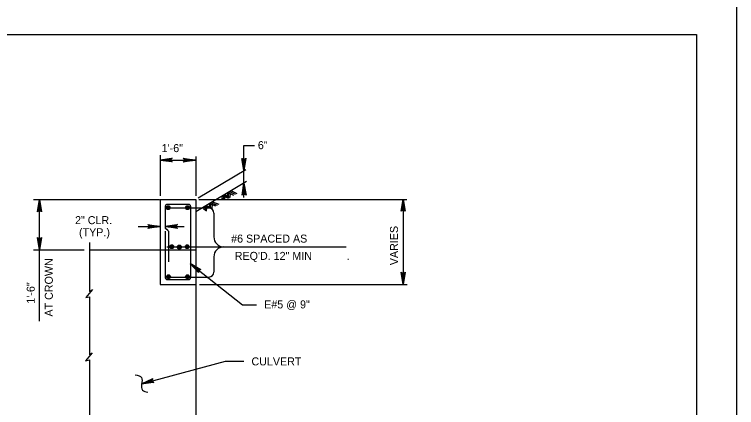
# Model space of a CAD drawing. Extents: x 639011 to 639866, y 298840 to 300028.
# Drawn here: x 639582.6 to 639852.3, y 299279.7 to 299426.3 of the extents above; entities that cross this region are included whole.
import ezdxf

# ---------------------------------------------------------------- set-up
doc = ezdxf.new("R2010")
doc.units = 0
doc.layers.add('2', color=7, linetype='Continuous')
doc.layers.add('PLT-BNDY', color=7, linetype='Continuous')

msp = doc.modelspace()

# ---------------------------------------------------------------- linework, layer by layer
at = {"layer": '2'}
for p, q in [((639051.26, 299418.83), (639837.26, 299418.83)), ((639837.26, 299418.83), (639837.26, 298854.83)), ((639668.28, 299377.41), (639672.26, 299377.41)), ((639668.28, 299368.11), (639668.28, 299377.41)), ((639636.93, 299373.81), (639636.93, 299358.66)), ((639636.93, 299373.81), (639636.93, 299358.66)), ((639650.28, 299373.36), (639650.28, 299358.66)), ((639650.28, 299373.36), (639650.28, 299358.66)), ((639636.93, 299372.01), (639641.48, 299372.77)), ((639641.25, 299372.56), (639636.93, 299372.01)), ((639636.93, 299372.01), (639641.09, 299372.24)), ((639636.93, 299372.01), (639641.1, 299372.03)), ((639636.93, 299372.01), (639650.13, 299372.01)), ((639641.1, 299371.81), (639636.93, 299372.01)), ((639636.93, 299372.01), (639641.26, 299371.49)), ((639641.49, 299371.3), (639636.93, 299372.01)), ((639641.09, 299372.24), (639641.25, 299372.56)), ((639641.1, 299371.81), (639641.09, 299372.24)), ((639641.26, 299371.49), (639641.1, 299371.81)), ((639641.48, 299372.77), (639641.25, 299372.56)), ((639641.26, 299371.49), (639641.49, 299371.3)), ((639645.8, 299372.52), (639645.57, 299372.72)), ((639645.57, 299372.72), (639650.13, 299372.01)), ((639650.13, 299372.01), (639645.58, 299371.25)), ((639645.58, 299371.25), (639645.81, 299371.46)), ((639645.8, 299372.52), (639645.96, 299372.21)), ((639650.13, 299372.01), (639645.8, 299372.52)), ((639645.81, 299371.46), (639650.13, 299372.01)), ((639645.96, 299371.77), (639645.81, 299371.46)), ((639645.96, 299372.21), (639650.13, 299372.01)), ((639645.96, 299372.21), (639645.96, 299371.77)), ((639650.13, 299372.01), (639645.96, 299371.77)), ((639650.13, 299372.01), (639645.96, 299371.99)), ((639668.28, 299368.11), (639667.52, 299372.66)), ((639667.52, 299372.66), (639667.73, 299372.43)), ((639668.04, 299372.27), (639667.73, 299372.43)), ((639667.73, 299372.43), (639668.28, 299368.11)), ((639668.48, 299372.28), (639668.04, 299372.27)), ((639668.28, 299368.11), (639668.04, 299372.27)), ((639668.28, 299368.11), (639668.26, 299372.27)), ((639668.99, 299372.67), (639668.28, 299368.11)), ((639668.28, 299368.11), (639668.8, 299372.44)), ((639668.48, 299372.28), (639668.28, 299368.11)), ((639668.8, 299372.44), (639668.48, 299372.28)), ((639668.8, 299372.44), (639668.99, 299372.67)), ((639651.18, 299357.91), (639669.01, 299368.55)), ((639668.28, 299363.46), (639668.28, 299368.11)), ((639650.28, 299352.87), (639669.17, 299364.14)), ((639667.57, 299358.9), (639668.28, 299363.46)), ((639668.28, 299363.46), (639667.76, 299359.13)), ((639668.08, 299359.29), (639668.28, 299363.46)), ((639668.28, 299358.06), (639668.28, 299363.46)), ((639668.28, 299363.46), (639668.51, 299359.29)), ((639668.83, 299359.14), (639668.28, 299363.46)), ((639668.28, 299363.46), (639669.04, 299358.9)), ((639668.28, 299363.46), (639668.3, 299359.29)), ((639662.14, 299359.95), (639661.98, 299358.69)), ((639662.13, 299359.86), (639661.98, 299358.66)), ((639662.13, 299360.01), (639664.38, 299358.96)), ((639662.19, 299359.98), (639664.38, 299358.96)), ((639662.59, 299359.79), (639662.43, 299358.51)), ((639662.73, 299360.31), (639664.98, 299359.26)), ((639662.74, 299360.3), (639664.98, 299359.26)), ((639663.28, 299360.63), (639665.58, 299359.56)), ((639663.33, 299360.61), (639665.58, 299359.56)), ((639589.68, 299357.31), (639636.78, 299357.31)), ((639589.68, 299357.31), (639636.78, 299357.31)), ((639591.22, 299352.75), (639591.93, 299357.31)), ((639591.93, 299357.31), (639591.41, 299352.98)), ((639591.73, 299353.14), (639591.93, 299357.31)), ((639591.93, 299338.56), (639591.93, 299357.31)), ((639591.93, 299357.31), (639592.16, 299353.14)), ((639592.47, 299352.99), (639591.93, 299357.31)), ((639591.93, 299357.31), (639592.69, 299352.75)), ((639591.93, 299357.31), (639591.94, 299353.14)), ((639636.93, 299357.31), (639650.28, 299357.31)), ((639636.93, 299357.31), (639636.93, 299329.56)), ((639636.93, 299357.31), (639650.28, 299357.31)), ((639636.93, 299357.31), (639636.93, 299329.56)), ((639650.28, 299357.31), (639650.28, 299228.46)), ((639651.48, 299357.31), (639729.08, 299357.31)), ((639651.48, 299357.31), (639729.08, 299357.31)), ((639660.18, 299358.81), (639660.03, 299357.46)), ((639660.18, 299358.77), (639660.03, 299357.46)), ((639660.18, 299358.81), (639662.43, 299357.76)), ((639660.21, 299358.79), (639662.43, 299357.76)), ((639660.48, 299358.96), (639662.73, 299357.91)), ((639660.48, 299358.96), (639662.73, 299357.91)), ((639660.64, 299358.59), (639660.48, 299357.31)), ((639660.63, 299358.51), (639660.48, 299357.31)), ((639660.81, 299359.15), (639663.18, 299358.21)), ((639660.93, 299359.11), (639663.18, 299358.21)), ((639661.08, 299358.39), (639660.93, 299357.01)), ((639661.08, 299358.36), (639660.93, 299357.01)), ((639662.58, 299359.71), (639662.43, 299358.51)), ((639663.18, 299359.56), (639663.03, 299358.21)), ((639663.17, 299359.52), (639663.04, 299358.27)), ((639667.76, 299359.13), (639667.57, 299358.9)), ((639667.76, 299359.13), (639668.08, 299359.29)), ((639668.08, 299359.29), (639668.51, 299359.29)), ((639668.51, 299359.29), (639668.83, 299359.14)), ((639669.04, 299358.9), (639668.83, 299359.14)), ((639727.02, 299352.9), (639727.73, 299357.46)), ((639727.73, 299357.46), (639727.21, 299353.13)), ((639727.53, 299353.29), (639727.73, 299357.46)), ((639727.73, 299357.46), (639727.73, 299325.66)), ((639727.73, 299357.46), (639727.96, 299353.29)), ((639728.28, 299353.14), (639727.73, 299357.46)), ((639727.73, 299357.46), (639728.49, 299352.9)), ((639727.73, 299357.46), (639727.74, 299353.29)), ((639638.88, 299354.8), (639638.88, 299346.66)), ((639638.88, 299354.76), (639638.88, 299346.66)), ((639639.48, 299355.51), (639647.73, 299355.51)), ((639639.52, 299355.51), (639647.67, 299355.51)), ((639648.33, 299354.82), (639648.33, 299328.17)), ((639648.33, 299354.76), (639648.33, 299328.21)), ((639653.43, 299354.61), (639653.28, 299353.41)), ((639653.43, 299354.61), (639653.28, 299353.41)), ((639653.29, 299354.67), (639654.48, 299354.16)), ((639653.43, 299354.61), (639654.48, 299354.16)), ((639653.71, 299354.92), (639654.93, 299354.31)), ((639653.73, 299354.91), (639654.93, 299354.31)), ((639653.88, 299354.46), (639653.73, 299353.11)), ((639653.88, 299354.46), (639653.73, 299353.11)), ((639654.05, 299355.12), (639656.43, 299354.01)), ((639654.18, 299355.06), (639656.43, 299354.01)), ((639655.38, 299355.81), (639655.23, 299354.61)), ((639655.38, 299355.81), (639655.23, 299354.61)), ((639655.27, 299355.85), (639657.63, 299354.91)), ((639655.38, 299355.81), (639657.63, 299354.91)), ((639655.83, 299355.66), (639655.68, 299354.31)), ((639655.83, 299355.66), (639655.68, 299354.31)), ((639655.82, 299356.17), (639658.23, 299355.21)), ((639655.98, 299356.11), (639658.23, 299355.21)), ((639656.43, 299355.36), (639656.28, 299354.16)), ((639656.43, 299355.36), (639656.28, 299354.16)), ((639656.36, 299356.5), (639658.83, 299355.51)), ((639656.58, 299356.41), (639658.83, 299355.51)), ((639591.41, 299352.98), (639591.22, 299352.75)), ((639591.41, 299352.98), (639591.73, 299353.14)), ((639591.73, 299353.14), (639592.16, 299353.14)), ((639592.16, 299353.14), (639592.47, 299352.99)), ((639592.69, 299352.75), (639592.47, 299352.99)), ((639639.33, 299354.16), (639655.23, 299354.16)), ((639639.33, 299354.16), (639655.23, 299354.16)), ((639654.33, 299354.16), (639654.18, 299352.96)), ((639654.33, 299354.16), (639654.18, 299352.96)), ((639657.03, 299352.21), (639657.03, 299343.36)), ((639657.03, 299352.21), (639657.03, 299343.36)), ((639727.21, 299353.13), (639727.02, 299352.9)), ((639727.21, 299353.13), (639727.53, 299353.29)), ((639727.53, 299353.29), (639727.96, 299353.29)), ((639727.96, 299353.29), (639728.28, 299353.14)), ((639728.49, 299352.9), (639728.28, 299353.14)), ((639628.82, 299347.26), (639636.93, 299347.26)), ((639632.6, 299347.77), (639632.37, 299347.97)), ((639632.37, 299347.97), (639636.93, 299347.26)), ((639636.93, 299347.26), (639632.38, 299346.5)), ((639632.38, 299346.5), (639632.61, 299346.71)), ((639632.6, 299347.77), (639632.76, 299347.46)), ((639636.93, 299347.26), (639632.6, 299347.77)), ((639632.61, 299346.71), (639636.93, 299347.26)), ((639632.76, 299347.02), (639632.61, 299346.71)), ((639632.76, 299347.46), (639636.93, 299347.26)), ((639632.76, 299347.46), (639632.76, 299347.02)), ((639636.93, 299347.26), (639632.76, 299347.02)), ((639636.93, 299347.26), (639632.76, 299347.24)), ((639638.88, 299347.26), (639643.43, 299348.02)), ((639643.2, 299347.81), (639638.88, 299347.26)), ((639638.88, 299347.26), (639643.04, 299347.49)), ((639638.88, 299347.26), (639643.05, 299347.28)), ((639638.88, 299347.26), (639645.97, 299347.26)), ((639643.05, 299347.06), (639638.88, 299347.26)), ((639638.88, 299347.26), (639643.21, 299346.74)), ((639643.44, 299346.55), (639638.88, 299347.26)), ((639640.09, 299345.45), (639638.88, 299346.66)), ((639639.78, 299345.76), (639638.88, 299346.66)), ((639643.04, 299347.49), (639643.2, 299347.81)), ((639643.05, 299347.06), (639643.04, 299347.49)), ((639643.21, 299346.74), (639643.05, 299347.06)), ((639643.43, 299348.02), (639643.2, 299347.81)), ((639643.21, 299346.74), (639643.44, 299346.55)), ((639638.88, 299345.46), (639638.88, 299329.56)), ((639638.88, 299345.46), (639638.88, 299329.56)), ((639640.08, 299345.46), (639640.08, 299334.06)), ((639591.93, 299338.56), (639591.16, 299343.11)), ((639591.16, 299343.11), (639591.38, 299342.88)), ((639591.69, 299342.72), (639591.38, 299342.88)), ((639591.38, 299342.88), (639591.93, 299338.56)), ((639592.12, 299342.73), (639591.69, 299342.72)), ((639591.93, 299338.56), (639591.69, 299342.72)), ((639591.93, 299338.56), (639591.91, 299342.72)), ((639592.63, 299343.12), (639591.93, 299338.56)), ((639591.93, 299338.56), (639592.44, 299342.89)), ((639592.12, 299342.73), (639591.93, 299338.56)), ((639592.44, 299342.89), (639592.12, 299342.73)), ((639592.44, 299342.89), (639592.63, 299343.12)), ((639610.53, 299341.26), (639610.53, 299322.96)), ((639589.68, 299338.56), (639608.54, 299338.56)), ((639591.93, 299311.97), (639591.93, 299338.56)), ((639610.68, 299338.56), (639637.08, 299338.56)), ((639637.08, 299338.56), (639650.13, 299338.56)), ((639637.08, 299338.56), (639650.13, 299338.56)), ((639639.48, 299339.61), (639659.73, 299339.61)), ((639641.98, 299339.61), (639659.73, 299339.61)), ((639660.78, 299339.61), (639706.5, 299339.61)), ((639660.78, 299339.61), (639671.73, 299339.61)), ((639657.03, 299335.86), (639657.03, 299330.31)), ((639657.03, 299335.86), (639657.03, 299330.31)), ((639648.18, 299333.46), (639667.68, 299318.01)), ((639651.32, 299330.71), (639648.18, 299333.46)), ((639648.18, 299333.46), (639651.25, 299330.36)), ((639651.31, 299330.07), (639648.18, 299333.46)), ((639648.18, 299333.46), (639651.59, 299331.06)), ((639651.9, 299331.21), (639648.18, 299333.46)), ((639648.18, 299333.46), (639652.22, 299331.23)), ((639648.18, 299333.46), (639651.46, 299330.88)), ((639636.93, 299330.31), (639636.93, 299325.66)), ((639636.93, 299330.31), (639636.93, 299325.66)), ((639638.88, 299330.31), (639638.88, 299328.16)), ((639638.88, 299330.31), (639638.88, 299328.21)), ((639651.25, 299330.36), (639651.32, 299330.71)), ((639651.25, 299330.36), (639651.31, 299330.07)), ((639651.32, 299330.71), (639651.59, 299331.06)), ((639651.59, 299331.06), (639651.9, 299331.21)), ((639652.22, 299331.23), (639651.9, 299331.21)), ((639727.73, 299325.66), (639726.97, 299330.21)), ((639726.97, 299330.21), (639727.18, 299329.98)), ((639728.43, 299330.22), (639727.73, 299325.66)), ((639728.24, 299329.99), (639728.43, 299330.22)), ((639639.48, 299327.46), (639647.73, 299327.46)), ((639639.5, 299327.46), (639647.63, 299327.46)), ((639639.93, 299328.36), (639655.23, 299328.36)), ((639639.93, 299328.36), (639655.23, 299328.36)), ((639727.49, 299329.82), (639727.18, 299329.98)), ((639727.18, 299329.98), (639727.73, 299325.66)), ((639727.93, 299329.83), (639727.49, 299329.82)), ((639727.73, 299325.66), (639727.49, 299329.82)), ((639727.73, 299325.66), (639727.71, 299329.82)), ((639727.73, 299325.66), (639728.24, 299329.99)), ((639727.93, 299329.83), (639727.73, 299325.66)), ((639728.24, 299329.99), (639727.93, 299329.83)), ((639636.93, 299325.66), (639650.13, 299325.66)), ((639636.93, 299325.66), (639650.13, 299325.66)), ((639651.63, 299325.66), (639729.23, 299325.66)), ((639651.63, 299325.66), (639729.23, 299325.66)), ((639611.73, 299323.71), (639609.18, 299320.71)), ((639610.53, 299322.96), (639611.73, 299323.71)), ((639609.18, 299320.71), (639610.53, 299321.01)), ((639610.53, 299321.01), (639610.53, 299299.41)), ((639667.68, 299318.01), (639672.93, 299318.01)), ((639611.58, 299300.16), (639609.03, 299297.16)), ((639610.53, 299299.41), (639611.58, 299300.16)), ((639609.03, 299297.16), (639610.53, 299297.46)), ((639610.53, 299297.46), (639610.53, 299273.46)), ((639630.03, 299288.55), (639661.38, 299297.01)), ((639661.38, 299297.01), (639668.28, 299297.01)), ((639630.03, 299288.55), (639634.22, 299290.48)), ((639634.05, 299290.21), (639630.03, 299288.55)), ((639630.03, 299288.55), (639633.99, 299289.87)), ((639630.03, 299288.55), (639634.04, 299289.66)), ((639633.99, 299289.87), (639634.05, 299290.21)), ((639634.1, 299289.45), (639633.99, 299289.87)), ((639634.22, 299290.48), (639634.05, 299290.21)), ((639634.1, 299289.45), (639630.03, 299288.55)), ((639630.03, 299288.55), (639634.34, 299289.18)), ((639634.62, 299289.06), (639630.03, 299288.55)), ((639634.34, 299289.18), (639634.1, 299289.45)), ((639634.34, 299289.18), (639634.62, 299289.06))]:
    msp.add_line(p, q, dxfattribs=at)
for centre, radius in [((639639.96, 299354.26), 0.715), ((639639.96, 299354.26), 0.715), ((639639.96, 299354.26), 0.511), ((639639.96, 299354.26), 0.511), ((639639.96, 299354.26), 0.279), ((639639.96, 299354.26), 0.279), ((639639.96, 299354.26), 0.141), ((639639.96, 299354.26), 0.141), ((639647.17, 299354.26), 0.715), ((639647.17, 299354.26), 0.715), ((639647.17, 299354.26), 0.511), ((639647.17, 299354.26), 0.511), ((639647.17, 299354.26), 0.279), ((639647.17, 299354.26), 0.279), ((639647.17, 299354.26), 0.141), ((639647.17, 299354.26), 0.141), ((639639.96, 299354.26), 0.0604), ((639639.96, 299354.26), 0.0604), ((639647.17, 299354.26), 0.0604), ((639647.17, 299354.26), 0.0604), ((639641.29, 299339.7), 0.715), ((639641.29, 299339.7), 0.715), ((639641.29, 299339.7), 0.511), ((639641.29, 299339.7), 0.511), ((639641.29, 299339.7), 0.279), ((639641.29, 299339.7), 0.279), ((639641.29, 299339.7), 0.141), ((639641.29, 299339.7), 0.141), ((639641.29, 299339.7), 0.0604), ((639641.29, 299339.7), 0.0604), ((639644.14, 299339.58), 0.715), ((639644.14, 299339.58), 0.715), ((639644.14, 299339.58), 0.511), ((639644.14, 299339.58), 0.511), ((639644.14, 299339.58), 0.279), ((639644.14, 299339.58), 0.279), ((639644.14, 299339.58), 0.141), ((639644.14, 299339.58), 0.141), ((639644.14, 299339.58), 0.0604), ((639644.14, 299339.58), 0.0604), ((639647.08, 299339.7), 0.715), ((639647.08, 299339.7), 0.715), ((639647.08, 299339.7), 0.511), ((639647.08, 299339.7), 0.511), ((639647.08, 299339.7), 0.279), ((639647.08, 299339.7), 0.279), ((639647.08, 299339.7), 0.141), ((639647.08, 299339.7), 0.141), ((639647.08, 299339.7), 0.0604), ((639647.08, 299339.7), 0.0604), ((639640.07, 299328.5), 0.715), ((639640.07, 299328.5), 0.715), ((639640.07, 299328.5), 0.511), ((639640.07, 299328.5), 0.511), ((639640.07, 299328.5), 0.279), ((639640.07, 299328.5), 0.279), ((639640.07, 299328.5), 0.141), ((639640.07, 299328.5), 0.141), ((639640.07, 299328.5), 0.0604), ((639640.07, 299328.5), 0.0604), ((639647.21, 299328.51), 0.715), ((639647.21, 299328.51), 0.715), ((639647.21, 299328.51), 0.511), ((639647.21, 299328.51), 0.511), ((639647.21, 299328.51), 0.279), ((639647.21, 299328.51), 0.279), ((639647.21, 299328.51), 0.141), ((639647.21, 299328.51), 0.141), ((639647.21, 299328.51), 0.0604), ((639647.21, 299328.51), 0.0604)]:
    msp.add_circle(centre, radius, dxfattribs=at)
for centre, radius, start, end in [((639639.59, 299354.81), 0.696, 90, 180), ((639647.62, 299354.81), 0.696, 0, 90), ((639655.18, 299352.25), 1.86, 0, 90), ((639655.18, 299352.25), 1.86, 0, 90), ((639660.75, 299343.34), 3.71, 180, 270), ((639660.75, 299343.34), 3.71, 180, 270), ((639660.75, 299335.91), 3.71, 90, 180), ((639660.75, 299335.91), 3.71, 90, 180), ((639655.18, 299330.24), 1.86, 270, 0), ((639655.18, 299330.24), 1.86, 270, 0), ((639639.57, 299328.16), 0.696, 180, 270), ((639647.64, 299328.16), 0.696, 270, 0)]:
    msp.add_arc(centre, radius, start, end, dxfattribs=at)
msp.add_spline([(639627.63, 299291.91), (639630.03, 299290.86), (639630.03, 299288.46), (639630.33, 299286.21), (639632.43, 299285.46)], degree=3, dxfattribs=at)
at = {"layer": 'PLT-BNDY'}
msp.add_lwpolyline([(639011.26, 299433.83), (639852.26, 299433.83), (639852.26, 298839.83), (639011.26, 298839.83)], close=True, dxfattribs=at)

# ---------------------------------------------------------------- texts
at = {"layer": '2'}
for s, height, p in [('6"', 2.988, (639673.47, 299376.08)), ('1\'-6"', 2.988, (639637.54, 299374.98)), ('2" CLR.', 2.988, (639605.19, 299348.11)), ('(TYP.)', 2.988, (639606.68, 299343.59)), ('#6 SPACED AS', 2.988, (639663.49, 299341.23)), ('REQ\'D. 12" MIN', 2.988, (639664.84, 299334.78)), ('.', 2.99, (639706.67, 299334.78)), ('E#5 @ 9"', 2.988, (639675.84, 299316.69)), ('CULVERT', 2.988, (639671.08, 299295.43))]:
    msp.add_text(s, height=height, dxfattribs=at).set_placement(p)
for s, p in [('VARIES', (639725.81, 299332.8)), ('AT CROWN', (639596.88, 299313.64)), ('1\'-6"', (639590.12, 299318.46))]:
    msp.add_text(s, height=2.988, rotation=90, dxfattribs=at).set_placement(p)

doc.saveas('drawing.dxf')
